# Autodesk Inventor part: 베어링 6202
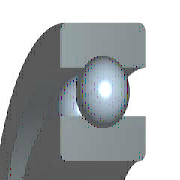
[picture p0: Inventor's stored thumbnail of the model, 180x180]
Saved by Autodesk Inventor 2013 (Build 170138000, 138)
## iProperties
Created: 2009-02
Part Number: 베어링 6202
Material: 강, 연강
Description: 깊은 그루브 볼 베어링
Document SubType Name: Modeling
Standard: KS B 2023
Designer: KYOUNG IL JANG
Standards Organization: KS
Language: ko-KR
Size Designation: 6202 - 15 x 35 x 11
Categories: <MemberInstance><Categories><Category DisplayName="샤프트 부품" InternalName="7f7aeb1f-a693-4053-b835-cee3144e0d98" Mnemonic="SHFT"><Category DisplayName="베어링" Inter
Density: 7.86 g/cm^3
Mass: 45.8724 g
Surface Area: 51.5584 cm^2
Volume: 5.83618 cm^3
Vendor: CBT Solutions
Company: 한국ATC센터
IsCustomPart: 1
Author: KYOUNG IL JANG
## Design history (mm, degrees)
sketch "스케치" dims "d0" = 5.2 (= -0.26 x WD + 0.26 x BD)
  geometry: L1 (2.9, 12.5)-(8.1, 12.5); L2 (5.5, 12.5)-(5.5, 9.9); L3 (5.5, 12.5)-(5.5, 15.1); L4 (3.568, 10.76)-(0, 10.76); L5 (0, 7.5)-(11, 7.5); L6 (3.568, 14.24)-(0, 14.24); L7 (0, 17.5)-(11, 17.5); L8 (11, 7.5)-(11, 10.76); L9 (7.432, 10.76)-(11, 10.76); L10 (7.432, 14.24)-(11, 14.24); L11 (11, 17.5)-(11, 14.24); L12 (-1.4, 0)-(8.4, 0) reference; L13 (0, -0.3)-(0, 5.3) reference
  constraints: 22 end point, 4 point on line, 2 collinear, 2 perpendicular, 2 symmetric about line, 1 midpoint, 1 parallel, 14 other
  dimensions: "d9" = 15 diameter of L5 L12 (= WD); "d11" = 35 diameter of L7 L12 (= BD); "d12" = 11 distance between parallel lines of L8 L13 (= KB); "d13" = 21.52 diameter of L9 L12 (= 0.326 x BD + 0.674 x WD)
revolve "본체" stored, may be unused: angle "d6" = 90 deg
revolve "볼" stored, may be unused: angle "d7" = 90 deg
pattern_circular "IDS_ARRAYBALL[SIMPL:T]" dims angle "d3" = 360 deg
body "Solid1"
fillet "모깎기1" dims "d1" = 0.6 (= KRS)
other parameters: "WD" = 15 [user parameter; used in 5 equation terms], "BD" = 35 [user parameter; used in 5 equation terms], "KB" = 11 [user parameter; used in 1 equation term], "KRS" = 0.6 [user parameter; used in 1 equation term], "d4" = 0, "d5" = 0, "d8" = 0, "d14" = 0, "d15" = 0, "BBA" = 0 [user parameter], "BC0" = 3750000 [user parameter], "BC" = 7800000 [user parameter], "BR" = 17.5 (= 0.5 x BD) [user parameter], "WR" = 7.5 (= 0.5 x WD) [user parameter]
